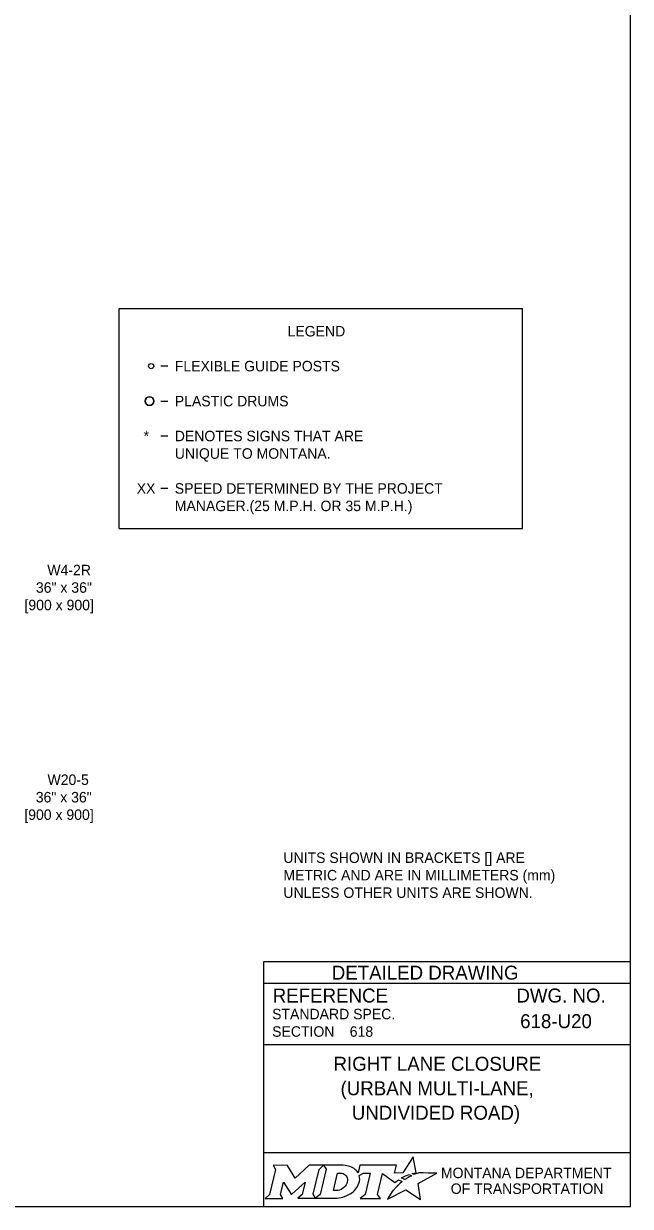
# Model space of a CAD drawing. Extents: x 49991.4 to 50021, y 49987.6 to 50011.4.
# Drawn here: x 50005.14 to 50008.61, y 50000.06 to 50006.83 of the extents above; entities that cross this region are included whole.
import ezdxf

# ---------------------------------------------------------------- set-up
doc = ezdxf.new("R2010")
doc.units = 0
doc.layers.add('Level 1', color=7, linetype='Continuous')
doc.layers.add('Level 2', color=7, linetype='Continuous')

msp = doc.modelspace()

# ---------------------------------------------------------------- linework, layer by layer
at = {"layer": 'Level 1'}
msp.add_lwpolyline([(50008.6146, 50011.2628), (50000.3356, 50011.2628), (50000.3356, 50000.0624), (50008.6146, 50000.0624)], close=True, dxfattribs=at)
for centre, radius in [((50005.8729, 50004.8712), 0.015), ((50005.8629, 50004.6712), 0.025)]:
    msp.add_circle(centre, radius, dxfattribs=at)
for start, end in [(360, 180), (180, 0)]:
    msp.add_arc((50005.8629, 50004.6712), 0.025, start, end, dxfattribs=at)
at = {"layer": 'Level 2'}
for p, q in [((50005.6901, 50005.2012), (50007.9968, 50005.2012)), ((50005.6901, 50003.9412), (50005.6901, 50005.2012)), ((50007.9968, 50003.9412), (50007.9968, 50005.2012)), ((50005.9679, 50004.8712), (50005.9279, 50004.8712)), ((50005.9279, 50004.6712), (50005.9679, 50004.6712)), ((50005.9679, 50004.4712), (50005.9279, 50004.4712)), ((50005.9679, 50004.1712), (50005.9279, 50004.1712)), ((50005.6901, 50003.9412), (50007.9968, 50003.9412)), ((50008.6146, 50001.4624), (50006.5146, 50001.4624)), ((50006.5146, 50001.4624), (50006.5146, 50000.0624)), ((50008.6146, 50001.3374), (50006.5146, 50001.3374)), ((50008.2507, 50001.1223), (50008.2507, 50001.1223)), ((50007.0089, 50001.0629), (50007.0089, 50001.0629)), ((50008.6146, 50000.9874), (50006.5146, 50000.9874)), ((50007.5646, 50000.7383), (50007.5646, 50000.7383)), ((50008.6146, 50000.3693), (50006.5146, 50000.3693))]:
    msp.add_line(p, q, dxfattribs=at)
for points in [[(50007.3771, 50000.2447), (50007.3668, 50000.2503), (50007.3784, 50000.2531), (50007.39, 50000.2551), (50007.3726, 50000.3452), (50007.3131, 50000.2539), (50007.2658, 50000.2532), (50007.2761, 50000.2973), (50007.0669, 50000.2974), (50007.0568, 50000.2549), (50007.051, 50000.2632)], [(50006.5701, 50000.2974), (50006.5842, 50000.274), (50006.5507, 50000.1307), (50006.525, 50000.1082), (50006.6266, 50000.1082), (50006.6131, 50000.131), (50006.6293, 50000.2011), (50006.673, 50000.1321), (50006.6783, 50000.1321), (50006.7534, 50000.2016), (50006.737, 50000.1305), (50006.7123, 50000.1085), (50006.8139, 50000.1085), (50006.8001, 50000.1318), (50006.8333, 50000.2742)], [(50006.8333, 50000.2742), (50006.8586, 50000.2974), (50006.7762, 50000.2974), (50006.6966, 50000.2244), (50006.6521, 50000.2971), (50006.5701, 50000.2974)], [(50006.9722, 50000.2974), (50006.8586, 50000.2974), (50006.8733, 50000.2745), (50006.8394, 50000.1307), (50006.8139, 50000.1085), (50006.9245, 50000.1085)], [(50006.9962, 50000.2107), (50006.995, 50000.2026), (50006.9918, 50000.1933), (50006.9876, 50000.1851), (50006.982, 50000.1776), (50006.9755, 50000.1707), (50006.9676, 50000.1644), (50006.9593, 50000.1597), (50006.9502, 50000.1558), (50006.9411, 50000.1535), (50006.9319, 50000.1526), (50006.916, 50000.1526), (50006.9396, 50000.2526), (50006.9556, 50000.2526), (50006.9632, 50000.252), (50006.9708, 50000.2501), (50006.9774, 50000.2471), (50006.9835, 50000.2429), (50006.9883, 50000.2379), (50006.992, 50000.2319), (50006.9947, 50000.2257), (50006.9963, 50000.2183), (50006.9963, 50000.2153), (50006.9962, 50000.2107)], [(50007.0636, 50000.2383), (50007.0882, 50000.2514), (50007.1251, 50000.2514), (50007.0965, 50000.1309), (50007.069, 50000.1082), (50007.1852, 50000.1082), (50007.1682, 50000.1311), (50007.1964, 50000.2513), (50007.2677, 50000.1996), (50007.2888, 50000.2147), (50007.3085, 50000.2038)], [(50007.2527, 50000.1479), (50007.2374, 50000.1235), (50007.2327, 50000.116), (50007.2269, 50000.1074), (50007.2246, 50000.1031), (50007.3299, 50000.1562), (50007.4138, 50000.1011), (50007.4007, 50000.1938), (50007.5076, 50000.2522), (50007.4583, 50000.253), (50007.4282, 50000.2534), (50007.4074, 50000.2537), (50007.4006, 50000.2522), (50007.3957, 50000.251), (50007.3873, 50000.2487), (50007.3771, 50000.2447)], [(50007.3267, 50000.2171), (50007.3243, 50000.2154), (50007.306, 50000.225), (50007.3163, 50000.2307), (50007.3204, 50000.2329), (50007.329, 50000.2369), (50007.3347, 50000.2395), (50007.3426, 50000.2425), (50007.3499, 50000.2452), (50007.3617, 50000.2378), (50007.3577, 50000.2357), (50007.3531, 50000.2332), (50007.3489, 50000.231), (50007.3439, 50000.2281), (50007.342, 50000.227), (50007.3393, 50000.2254), (50007.3368, 50000.224), (50007.3345, 50000.2224), (50007.3319, 50000.2206), (50007.3292, 50000.2188), (50007.3267, 50000.2171)], [(50006.9702, 50000.1158), (50006.9786, 50000.1184), (50006.9916, 50000.1238), (50007.012, 50000.1348)], [(50007.2666, 50000.164), (50007.2666, 50000.164)]]:
    msp.add_lwpolyline(points, dxfattribs=at)
for centre, radius, start, end in [((50006.9513, 50000.2363), 0.1183, 300.91025, 339.13831), ((50006.9953, 50000.219), 0.0709, 339.53292, 15.85821)]:
    msp.add_arc(centre, radius, start, end, dxfattribs=at)
for centre, major_axis, ratio, start_param, end_param in [((50006.9701, 50000.25), (0.0834, -0.0037), 0.568097, 0.61298, 1.570796), ((50007.0257, 50000.2573), (0.0361, -0.0295), 0.469099, 1.225588, 1.570796), ((50007.2974, 50000.1941), (-0.0112, -0.0097), 0.021651, 3.157348, 6.283185), ((50007.2597, 50000.1559), (-0.00694, -0.00806), 0.008222, 0, 3.137361), ((50007.2764, 50000.1742), (-0.0098, -0.0102), 0.016458, 3.141593, 6.279097), ((50006.9248, 50000.2568), (0, 0.1484), 0.987302, 3.139398, 3.456847)]:
    msp.add_ellipse(centre, major_axis=major_axis, ratio=ratio, start_param=start_param, end_param=end_param, dxfattribs=at)

# ---------------------------------------------------------------- texts
for s, height, p in [('LEGEND', 0.06, (50006.6533, 50005.0411)), ('FLEXIBLE GUIDE POSTS', 0.06, (50006.0079, 50004.8412)), ('PLASTIC DRUMS', 0.06, (50006.0079, 50004.6412)), ('*', 0.06, (50005.8293, 50004.4412)), ('DENOTES SIGNS THAT ARE', 0.06, (50006.0079, 50004.4412)), ('UNIQUE TO MONTANA.', 0.06, (50006.0079, 50004.3412)), ('XX', 0.06, (50005.7901, 50004.1412)), ('SPEED DETERMINED BY THE PROJECT', 0.06, (50006.0079, 50004.1412)), ('MANAGER.(25 M.P.H. OR 35 M.P.H.)', 0.06, (50006.0079, 50004.0412)), ('W4-2R', 0.06, (50005.2785, 50003.6741)), ('36" x 36"', 0.06, (50005.2134, 50003.5741)), ('[900 x 900]', 0.06, (50005.1478, 50003.4741)), ('W20-5', 0.06, (50005.2796, 50002.4741)), ('36" x 36"', 0.06, (50005.2125, 50002.3741)), ('[900 x 900]', 0.06, (50005.1469, 50002.2741)), ('UNITS SHOWN IN BRACKETS [] ARE ', 0.06, (50006.6294, 50002.0278)), ('METRIC AND ARE IN MILLIMETERS (mm) ', 0.06, (50006.6294, 50001.9278)), ('UNLESS OTHER UNITS ARE SHOWN.', 0.06, (50006.6294, 50001.8278)), ('DETAILED DRAWING', 0.0799, (50006.9063, 50001.3599)), ('REFERENCE', 0.08, (50006.5682, 50001.229)), ('DWG. NO.', 0.08, (50007.9624, 50001.229)), ('STANDARD SPEC.', 0.06, (50006.5649, 50001.133)), ('618-U20', 0.08, (50007.9841, 50001.0823)), ('SECTION', 0.06, (50006.5649, 50001.033)), ('618', 0.06, (50007.0089, 50001.0329)), (' RIGHT LANE CLOSURE', 0.08, (50006.8864, 50000.8383)), ('(URBAN MULTI-LANE,', 0.08, (50006.9564, 50000.6983)), ('UNDIVIDED ROAD)', 0.08, (50007.021, 50000.5583)), ('MONTANA DEPARTMENT', 0.06, (50007.5308, 50000.2236)), ('OF TRANSPORTATION', 0.06, (50007.587, 50000.1336))]:
    msp.add_text(s, height=height, dxfattribs=at).set_placement(p)

doc.saveas('drawing.dxf')
